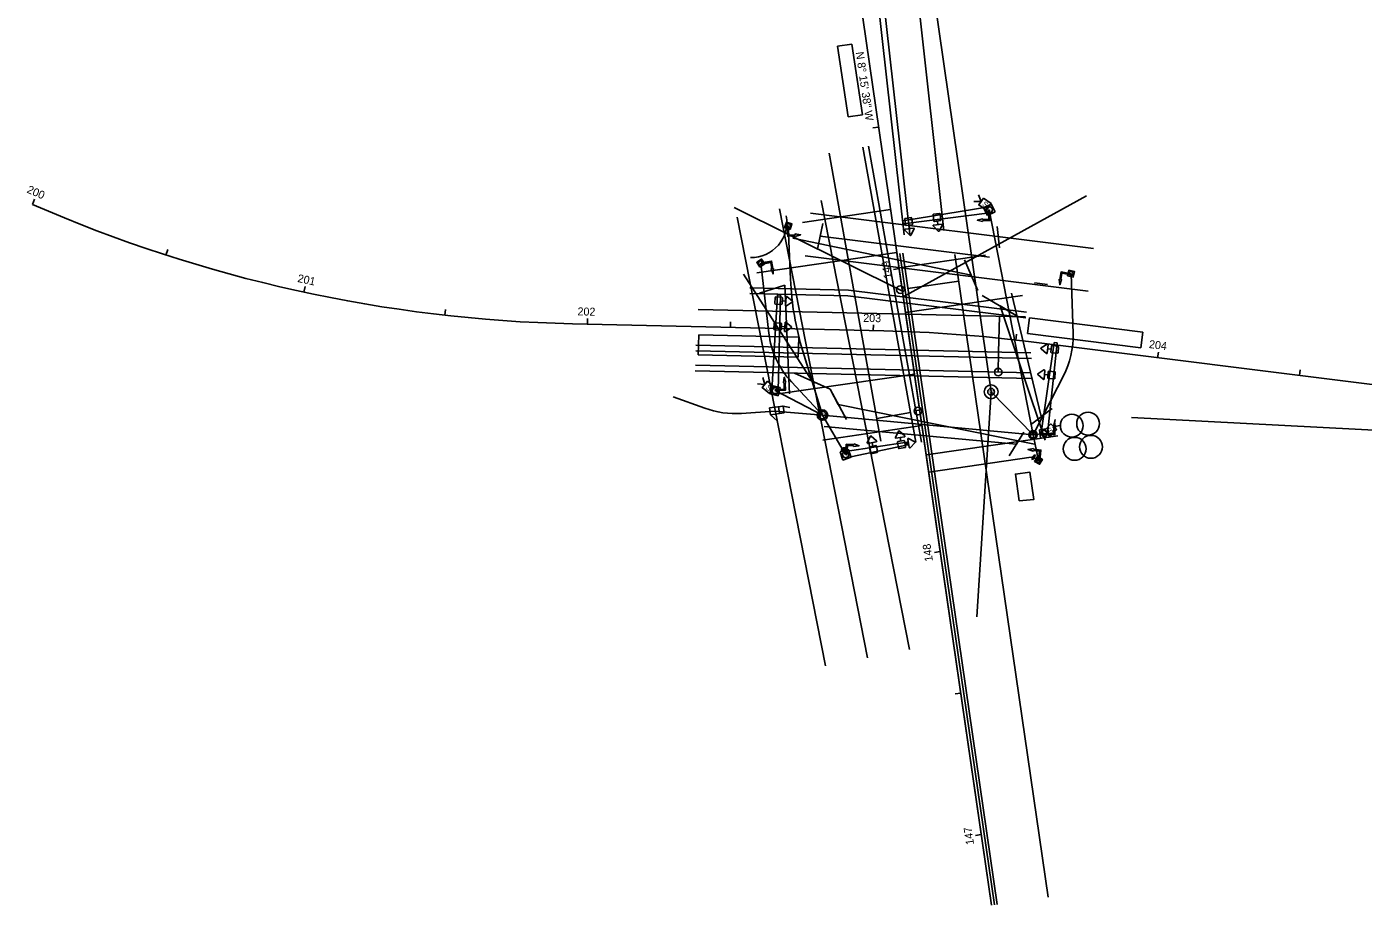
# Model space of a CAD drawing. Extents: x 1827063 to 1831280, y 711192 to 712800.
# Drawn here: x 1827845.4 to 1828313, y 711420.3 to 711727.6 of the extents above; entities that cross this region are included whole.
import ezdxf

# ---------------------------------------------------------------- set-up
doc = ezdxf.new("R2010")
doc.units = 0
for name, color, linetype in [('BR_P_Beam_Object', 7, 'Continuous'), ('BR_P_Gen_Joint_Filler', 7, 'Continuous'), ('Default', 7, 'Continuous'), ('DR_P_Storm_Sewer', 7, 'Continuous'), ('GE_P_CL_50', 7, 'Continuous'), ('PM_P_Crosswalk', 7, 'Continuous'), ('PV_P_Walk', 7, 'Continuous'), ('SC_Scratch6', 7, 'Continuous'), ('SG_P_Wiring', 7, 'Continuous'), ('SG_X_Controllers', 7, 'Continuous'), ('SG_X_Detection', 7, 'Continuous'), ('SG_X_Interconnect_Cable', 7, 'Continuous'), ('UT_P_Water', 7, 'Continuous'), ('UT_P_Water_Cells', 7, 'Continuous'), ('UT_P_Water_Text', 7, 'Continuous'), ('UT_X_Electric', 7, 'Continuous'), ('VG_X_Cells', 7, 'Continuous')]:
    doc.layers.add(name, color=color, linetype=linetype)

# ---------------------------------------------------------------- blocks, each defined once
blk = doc.blocks.new('SPOLE_1')
at = {"layer": 'Default'}
blk.add_circle((0, 0), 0.0138, dxfattribs=at)
blk = doc.blocks.new('Sighead')
at = {"layer": 'Default'}
for p, q in [((-0.03, 0.975), (-0.335, 0.569)), ((0.335, 0.569), (0.03, 0.975)), ((-0.305, 0.508), (0.305, 0.508)), ((-0.254, -0.216), (-0.254, 0.216)), ((-0.216, 0.254), (0.216, 0.254)), ((0, 0.508), (0, 0.254)), ((0.254, 0.216), (0.254, -0.216)), ((0.216, -0.254), (-0.216, -0.254))]:
    blk.add_line(p, q, dxfattribs=at)
for centre, start, end in [((0, 0.953), 36.8699, 143.1301), ((-0.305, 0.546), 143.1301, 270), ((-0.216, 0.216), 90, 180), ((0.216, 0.216), 0, 90), ((0.305, 0.546), 270, 36.8699), ((-0.216, -0.216), 180, 270), ((0.216, -0.216), 270, 0)]:
    blk.add_arc(centre, 0.0381, start, end, dxfattribs=at)
blk = doc.blocks.new('A$C70A22DE5')
at = {"layer": 'Default'}
for p, q in [((0, 0), (0.48, 0)), ((0.48, 0.24), (0.48, -0.24))]:
    blk.add_line(p, q, dxfattribs=at)
blk.add_arc((0.37, 0), 0.259, 294.3601, 65.6399, dxfattribs=at)

msp = doc.modelspace()

# ---------------------------------------------------------------- linework, layer by layer
at = {"layer": 'BR_P_Beam_Object'}
msp.add_line((1828154.76, 711660.82), (1828154.9, 711659.83), dxfattribs=at)
at = {"layer": 'BR_P_Gen_Joint_Filler'}
for centre in [(1828210.99, 711588.08), (1828216.7, 711588.78), (1828211.98, 711579.98), (1828217.69, 711580.68)]:
    msp.add_circle(centre, 4, dxfattribs=at)
at = {"layer": 'DR_P_Storm_Sewer'}
for p, q in [((1828182.93, 711420.35), (1828100.32, 711989.38)), ((1828143.42, 711692.49), (1828141.44, 711692.2)), ((1827847.36, 711665.45), (1827848.16, 711667.29)), ((1827894.09, 711647.74), (1827894.71, 711649.64)), ((1828150.6, 711643.01), (1828148.62, 711642.72)), ((1827942.36, 711634.78), (1827942.78, 711636.73)), ((1827991.69, 711626.7), (1827991.91, 711628.69)), ((1828036.34, 711623.69), (1828145.18, 711621.22)), ((1828041.57, 711623.57), (1828041.61, 711625.57)), ((1828091.56, 711622.44), (1828091.6, 711624.44)), ((1828141.54, 711621.31), (1828141.59, 711623.31)), ((1828191.41, 711618.03), (1828191.64, 711620.02)), ((1828195.88, 711617.49), (1828394.91, 711592.6)), ((1828241.03, 711611.84), (1828241.28, 711613.83)), ((1828290.64, 711605.64), (1828290.89, 711607.63)), ((1828157.79, 711593.53), (1828155.81, 711593.24)), ((1828164.97, 711544.05), (1828162.99, 711543.76)), ((1828172.15, 711494.57), (1828170.18, 711494.28)), ((1828179.34, 711445.09), (1828177.36, 711444.8))]:
    msp.add_line(p, q, dxfattribs=at)
for centre, start, end in [((1828047.65, 712123.23), 246.3698, 268.7041), ((1828133.88, 711121.68), 82.8726, 88.7041)]:
    msp.add_arc(centre, 499.67, start, end, dxfattribs=at)
at = {"layer": 'GE_P_CL_50'}
for p, q in [((1828123.3, 711666.79), (1828154.18, 711509.79)), ((1828093.97, 711661.02), (1828124.84, 711504.03)), ((1828093.97, 711661.02), (1828124.84, 711504.03)), ((1828108.68, 711663.91), (1828139.56, 711506.92)), ((1828108.68, 711663.91), (1828139.56, 711506.92)), ((1828108.68, 711663.91), (1828139.56, 711506.92)), ((1828108.68, 711663.91), (1828139.56, 711506.92))]:
    msp.add_line(p, q, dxfattribs=at)
at = {"layer": 'PM_P_Crosswalk'}
for p, q in [((1828132.68, 711633.51), (1828098.37, 711634.29)), ((1828132.83, 711635.51), (1828098.41, 711636.29)), ((1828132.68, 711633.51), (1828194.95, 711625.74)), ((1828132.83, 711635.51), (1828195.2, 711627.73))]:
    msp.add_line(p, q, dxfattribs=at)
at = {"layer": 'PV_P_Walk'}
for p, q in [((1828117.85, 711982.39), (1828154.28, 711655.03)), ((1828141.1, 711881.98), (1828166.21, 711656.36)), ((1828130.3, 711852.4), (1828152.3, 711654.81)), ((1828137.92, 711685.46), (1828156.42, 711582.33)), ((1828139.89, 711685.82), (1828158.46, 711582.28)), ((1828144.18, 711582.61), (1828126.11, 711683.35)), ((1828152.04, 711633.11), (1828216.18, 711668.44)), ((1828092.93, 711664.42), (1828151.76, 711635.08)), ((1828116.78, 711659.14), (1828147.61, 711663.62)), ((1828119.55, 711662.36), (1828218.55, 711650.02)), ((1828122.07, 711649.8), (1828123.93, 711658.79)), ((1828123.93, 711658.79), (1828123, 711654.3)), ((1828184.88, 711657.69), (1828185.71, 711650.32)), ((1828175.81, 711640.74), (1828113.44, 711653.69)), ((1828123, 711654.3), (1828182.19, 711646.95)), ((1828100.79, 711641.53), (1828149.79, 711648.64)), ((1828117.69, 711647.48), (1828216.7, 711635.13)), ((1828182.93, 711420.35), (1828149.82, 711648.42)), ((1828180.82, 711647.72), (1828150.56, 711643.33)), ((1828183.92, 711420.49), (1828150.86, 711648.23)), ((1828184.91, 711420.63), (1828151.85, 711648.38)), ((1828202.72, 711423.22), (1828170.09, 711647.96)), ((1828173.45, 711646.08), (1828178.16, 711635.4)), ((1828120.21, 711603.67), (1828096.19, 711641.04)), ((1828153.63, 711636.06), (1828171.45, 711638.65)), ((1828178.16, 711635.4), (1828175.81, 711640.74)), ((1828197.89, 711637.97), (1828202.47, 711637.4)), ((1828101.78, 711634.44), (1828110.6, 711637.17)), ((1828110.6, 711637.17), (1828112.19, 711599.25)), ((1828193.73, 711633.63), (1828152.83, 711627.69)), ((1828179.64, 711633.64), (1828192.17, 711626.25)), ((1828200.32, 711591.25), (1828189.91, 711634.44)), ((1828194.82, 711626.1), (1828080.28, 711628.69)), ((1828192.17, 711626.25), (1828185.9, 711629.95)), ((1828185.9, 711629.95), (1828201.62, 711583.06)), ((1828185.68, 711626.31), (1828185.4, 711613.8)), ((1828196.94, 711611.54), (1828079.44, 711614.19)), ((1828196.65, 711613.54), (1828079.48, 711616.19)), ((1828185.24, 711606.8), (1828185.4, 711613.8)), ((1828196.78, 711604.54), (1828079.28, 711607.2)), ((1828196.82, 711606.54), (1828079.32, 711609.2)), ((1828107.49, 711599.07), (1828155.96, 711606.11)), ((1828113.98, 711606.47), (1828126.43, 711600.87)), ((1828126.43, 711600.87), (1828120.21, 711603.67)), ((1828132.22, 711590.19), (1828126.43, 711600.87)), ((1828126.43, 711600.87), (1828129.32, 711595.53)), ((1828129.32, 711595.53), (1828198, 711581.61)), ((1828142.75, 711590.58), (1828154.56, 711592.7)), ((1828196.49, 711588.38), (1828204.14, 711594.11)), ((1828204.14, 711594.11), (1828200.32, 711591.25)), ((1828123.94, 711583.06), (1828158.58, 711588.09)), ((1828191.63, 711581.66), (1828124.35, 711587.74)), ((1828206.07, 711584.56), (1828160.06, 711577.88)), ((1828189.08, 711577.53), (1828194.18, 711585.79)), ((1828194.18, 711585.79), (1828191.63, 711581.66)), ((1828196.78, 711577.07), (1828160.93, 711571.86))]:
    msp.add_line(p, q, dxfattribs=at)
for centre in [(1828150.99, 711635.68), (1828185.24, 711606.8), (1828157.19, 711593.17)]:
    msp.add_circle(centre, 1.33, dxfattribs=at)
msp.add_arc((1828098.93, 711659.28), 12.39, 268.7041, 10.1696, dxfattribs=at)
at = {"layer": 'SC_Scratch6'}
for p, q in [((1828180.1, 711664.2), (1828182.77, 711665.56)), ((1828182.77, 711665.56), (1828184.14, 711662.89)), ((1828181.46, 711661.52), (1828180.1, 711664.2)), ((1828184.14, 711662.89), (1828181.46, 711661.52)), ((1828105.39, 711599.22), (1828106.07, 711602.15)), ((1828106.07, 711602.15), (1828108.99, 711601.47)), ((1828108.99, 711601.47), (1828108.31, 711598.54)), ((1828108.31, 711598.54), (1828105.39, 711599.22)), ((1828199.67, 711586.65), (1828202.64, 711587.08)), ((1828200.1, 711583.67), (1828199.67, 711586.65)), ((1828202.64, 711587.08), (1828203.07, 711584.11)), ((1828203.07, 711584.11), (1828200.1, 711583.67)), ((1828129.97, 711578.89), (1828132.81, 711579.85)), ((1828130.93, 711576.05), (1828129.97, 711578.89)), ((1828133.77, 711577.01), (1828130.93, 711576.05)), ((1828132.81, 711579.85), (1828133.77, 711577.01))]:
    msp.add_line(p, q, dxfattribs=at)
for points in [[(1828112.42, 711656.71), (1828110.53, 711657.36), (1828111.17, 711659.25), (1828113.07, 711658.61)], [(1828101.89, 711643.56), (1828100.79, 711645.23), (1828102.46, 711646.33), (1828103.56, 711644.66)], [(1828209.54, 711640.48), (1828209.96, 711642.44), (1828211.92, 711642.02), (1828211.49, 711640.06)], [(1828199.03, 711577.31), (1828200.74, 711576.27), (1828199.7, 711574.56), (1828197.99, 711575.6)]]:
    msp.add_lwpolyline(points, close=True, dxfattribs=at)
for centre in [(1828111.8, 711657.98), (1828102.17, 711644.94), (1828210.73, 711641.25), (1828199.37, 711575.94)]:
    msp.add_circle(centre, 0.727, dxfattribs=at)
for centre, start, end in [((1828182.12, 711663.54), 117.0406, 297.0406), ((1828182.12, 711663.54), 297.0406, 117.0406), ((1828107.19, 711600.35), 76.9134, 256.9134), ((1828107.19, 711600.35), 256.9134, 76.9134), ((1828201.37, 711585.38), 98.2605, 278.2605), ((1828201.37, 711585.38), 278.2605, 98.2605), ((1828131.87, 711577.95), 108.6322, 288.6322), ((1828131.87, 711577.95), 288.6322, 108.6322)]:
    msp.add_arc(centre, 1.09, start, end, dxfattribs=at)
at = {"layer": 'SG_P_Wiring'}
msp.add_line((1828197.45, 711584.9), (1828201.37, 711585.38), dxfattribs=at)
at = {"layer": 'SG_X_Controllers'}
for p, q in [((1828105.22, 711594.29), (1828110.01, 711594.95)), ((1828105.22, 711594.29), (1828105.55, 711591.9)), ((1828105.55, 711591.9), (1828110.34, 711592.56)), ((1828105.55, 711591.9), (1828107.9, 711589.77)), ((1828108.36, 711594.73), (1828108.68, 711592.33)), ((1828110.01, 711594.95), (1828110.34, 711592.56)), ((1828110.01, 711594.95), (1828112.37, 711594.44))]:
    msp.add_line(p, q, dxfattribs=at)
for centre in [(1828105.62, 711591.99), (1828109.94, 711594.86)]:
    msp.add_circle(centre, 0.0833, dxfattribs=at)
at = {"layer": 'SG_X_Detection'}
for p, q in [((1828129.05, 711720.79), (1828134, 711721.54)), ((1828132.79, 711696.07), (1828129.05, 711720.79)), ((1828134, 711721.54), (1828137.73, 711696.82)), ((1828137.73, 711696.82), (1828132.79, 711696.07)), ((1828176.7, 711666.48), (1828179.25, 711666.47)), ((1828178.31, 711668.83), (1828179.25, 711666.47)), ((1828195.47, 711620.31), (1828196.15, 711625.77)), ((1828196.15, 711625.77), (1828235.84, 711620.81)), ((1828080.33, 711612.79), (1828080.49, 711619.79)), ((1828080.49, 711619.79), (1828115.48, 711618.99)), ((1828115.48, 711618.99), (1828115.32, 711612)), ((1828235.16, 711615.35), (1828195.47, 711620.31)), ((1828235.84, 711620.81), (1828235.16, 711615.35)), ((1828115.32, 711612), (1828080.33, 711612.79)), ((1828102.88, 711604.96), (1828103.59, 711602.52)), ((1828101.06, 711602.76), (1828103.59, 711602.52)), ((1828205.15, 711590.21), (1828204.72, 711587.7)), ((1828207.2, 711588.24), (1828204.72, 711587.7))]:
    msp.add_line(p, q, dxfattribs=at)
for points in [[(1828180.05, 711667.64), (1828182.73, 711665.81), (1828181.13, 711663.46), (1828178.45, 711665.29)], [(1828104.5, 711603.61), (1828107.01, 711601.54), (1828105.19, 711599.35), (1828102.69, 711601.42)], [(1828205.75, 711586.72), (1828203.5, 711584.37), (1828201.44, 711586.34), (1828203.69, 711588.69)]]:
    msp.add_lwpolyline(points, close=True, dxfattribs=at)
at = {"layer": 'SG_X_Interconnect_Cable'}
for p, q in [((1828182.76, 711599.93), (1828149.39, 711832.03)), ((1828177.77, 711521.21), (1828182.76, 711599.93)), ((1828231.87, 711590.97), (1828404.99, 711581.92))]:
    msp.add_line(p, q, dxfattribs=at)
at = {"layer": 'UT_P_Water'}
for p, q in [((1828182.12, 711663.54), (1828197.45, 711584.9)), ((1828112.58, 711639.27), (1828111.8, 711657.98)), ((1828211.42, 711620.24), (1828210.73, 711641.25)), ((1828123.76, 711591.78), (1828116.9, 711614.14)), ((1828197.45, 711584.9), (1828208.08, 711605.46)), ((1828123.76, 711591.78), (1828107.19, 711600.35)), ((1828071.59, 711598.16), (1828082.56, 711594.23)), ((1828182.76, 711599.93), (1828197.45, 711584.9)), ((1828095.4, 711592.36), (1828107, 711593.2)), ((1828107, 711593.2), (1828123.76, 711591.78)), ((1828123.76, 711591.78), (1828131.87, 711577.95)), ((1828123.76, 711591.78), (1828197.45, 711584.9)), ((1828199.37, 711575.94), (1828197.45, 711584.9))]:
    msp.add_line(p, q, dxfattribs=at)
for points in [[(1828105.02, 711620.42), (1828102.17, 711644.94)], [(1828123.76, 711591.78), (1828112.9, 711603.39)]]:
    msp.add_lwpolyline(points, dxfattribs=at)
for centre, radius, start, end in [((1828212.5, 711643.48), 100, 182.4104, 197.0603), ((1828134.82, 711623.88), 30, 186.6123, 223.0804), ((1828181.44, 711619.25), 30, 332.641, 1.8972), ((1828093.21, 711622.28), 30, 249.2114, 274.1762)]:
    msp.add_arc(centre, radius, start, end, dxfattribs=at)
at = {"layer": 'UT_P_Water_Cells'}
for centre, radius in [((1828182.76, 711599.93), 2.42), ((1828182.76, 711599.93), 1.18), ((1828123.76, 711591.78), 1.83), ((1828123.76, 711591.78), 1.34), ((1828197.45, 711584.9), 1.46), ((1828197.45, 711584.9), 1.12), ((1828197.45, 711584.9), 1.12), ((1828197.45, 711584.9), 1.12), ((1828197.45, 711584.9), 1.12), ((1828197.45, 711584.9), 1.12)]:
    msp.add_circle(centre, radius, dxfattribs=at)
at = {"layer": 'UT_P_Water_Text'}
for p, q in [((1828151.86, 711659.66), (1828181.96, 711664.62)), ((1828182.27, 711662.46), (1828152.01, 711658.66)), ((1828152.01, 711658.66), (1828151.86, 711659.66)), ((1828106.1, 711600.39), (1828108.03, 711633.84)), ((1828108.03, 711633.84), (1828109.04, 711633.8)), ((1828109.04, 711633.8), (1828108.28, 711600.3)), ((1828200.28, 711585.51), (1828204.84, 711617.19)), ((1828205.84, 711617.07), (1828202.45, 711585.24)), ((1828204.84, 711617.19), (1828205.84, 711617.07)), ((1828131.68, 711579.02), (1828153.44, 711582.33)), ((1828153.61, 711581.33), (1828132.06, 711576.87)), ((1828153.44, 711582.33), (1828153.61, 711581.33))]:
    msp.add_line(p, q, dxfattribs=at)
for centre, start, end in [((1828182.12, 711663.54), 278.2767, 98.2767), ((1828107.19, 711600.35), 177.7307, 357.7307), ((1828201.37, 711585.38), 172.8889, 352.8889), ((1828131.87, 711577.95), 100.1859, 280.1859)]:
    msp.add_arc(centre, 1.09, start, end, dxfattribs=at)
at = {"layer": 'UT_X_Electric'}
msp.add_lwpolyline([(1828192.58, 711561.73), (1828197.77, 711562.29), (1828196.3, 711571.86), (1828191.26, 711571.15), (1828192.58, 711561.73)], dxfattribs=at)
at = {"layer": 'VG_X_Cells'}
for p, q in [((1828181.83, 711663.49), (1828182.23, 711663.51)), ((1828111.8, 711657.98), (1828111.4, 711657.96)), ((1828102.44, 711644.59), (1828102.37, 711644.99)), ((1828210.77, 711640.84), (1828210.83, 711641.23)), ((1828107.17, 711600.75), (1828107.19, 711600.35)), ((1828201.37, 711585.38), (1828201.35, 711584.98)), ((1828132.27, 711577.92), (1828131.87, 711577.95)), ((1828199.37, 711575.94), (1828199.76, 711575.89))]:
    msp.add_line(p, q, dxfattribs=at)
for points in [[(1828179.77, 711660.15), (1828181.98, 711660.24), (1828181.83, 711663.49)], [(1828182.23, 711663.51), (1828182.4, 711659.86), (1828179.79, 711659.75)], [(1828111.4, 711657.96), (1828111.62, 711654.31), (1828114.22, 711654.48)], [(1828114.2, 711654.87), (1828111.99, 711654.73), (1828111.8, 711657.98)], [(1828179.8, 711659.51), (1828177.89, 711659.91), (1828179.76, 711660.38), (1828179.77, 711660.15)], [(1828179.79, 711659.75), (1828179.8, 711659.51)], [(1828114.24, 711654.24), (1828116.09, 711654.84), (1828114.18, 711655.11), (1828114.2, 711654.87)], [(1828114.22, 711654.48), (1828114.24, 711654.24)], [(1828102.37, 711644.99), (1828105.97, 711645.61), (1828106.41, 711643.04)], [(1828106.02, 711642.97), (1828105.65, 711645.15), (1828102.44, 711644.59)], [(1828106.65, 711643.08), (1828106.49, 711641.14), (1828105.79, 711642.94), (1828106.02, 711642.97)], [(1828106.41, 711643.04), (1828106.65, 711643.08)], [(1828206.81, 711639.24), (1828206.58, 711639.27)], [(1828206.58, 711639.27), (1828206.76, 711637.33), (1828207.44, 711639.14), (1828207.21, 711639.18)], [(1828210.83, 711641.23), (1828207.22, 711641.82), (1828206.81, 711639.24)], [(1828207.21, 711639.18), (1828207.55, 711641.36), (1828210.77, 711640.84)], [(1828110.96, 711603.12), (1828110.39, 711604.98), (1828110.09, 711603.08), (1828110.33, 711603.09)], [(1828110.33, 711603.09), (1828110.42, 711600.88), (1828107.17, 711600.75)], [(1828107.19, 711600.35), (1828110.84, 711600.5), (1828110.73, 711603.11)], [(1828110.73, 711603.11), (1828110.96, 711603.12)], [(1828201.35, 711584.98), (1828205.01, 711584.85), (1828205.09, 711587.45)], [(1828204.69, 711587.47), (1828204.62, 711585.26), (1828201.37, 711585.38)], [(1828205.33, 711587.45), (1828204.91, 711589.35), (1828204.46, 711587.47), (1828204.69, 711587.47)], [(1828205.09, 711587.45), (1828205.33, 711587.45)], [(1828131.87, 711577.95), (1828132.09, 711581.6), (1828134.7, 711581.43)], [(1828134.71, 711581.67), (1828136.57, 711581.06), (1828134.65, 711580.8), (1828134.67, 711581.03)], [(1828134.7, 711581.43), (1828134.71, 711581.67)], [(1828134.67, 711581.03), (1828132.47, 711581.17), (1828132.27, 711577.92)], [(1828197.61, 711580.05), (1828195.68, 711579.77), (1828197.52, 711579.18), (1828197.54, 711579.41)], [(1828197.54, 711579.41), (1828199.74, 711579.17), (1828199.37, 711575.94)], [(1828197.58, 711579.81), (1828197.61, 711580.05)], [(1828199.76, 711575.89), (1828200.18, 711579.52), (1828197.58, 711579.81)]]:
    msp.add_lwpolyline(points, dxfattribs=at)

# ---------------------------------------------------------------- block references
at = {"layer": 'SC_Scratch6'}
for p, xscale, yscale, rotation in [((1828111.8, 711657.98), 52.49554118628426, 52.49554118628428, 161.16563581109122), ((1828102.17, 711644.94), 52.495541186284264, 52.49554118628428, 123.38965118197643), ((1828210.73, 711641.25), 52.49554118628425, 52.49554118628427, 77.81417194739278), ((1828199.37, 711575.94), 52.495541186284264, 52.49554118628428, -31.222800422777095)]:
    msp.add_blockref('SPOLE_1', p, dxfattribs=dict(at, xscale=xscale, yscale=yscale, rotation=rotation))
at = {"layer": 'SG_X_Detection'}
for p, xscale, yscale, rotation in [((1828131.87, 711577.95), 3.9417244, 3.941724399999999, 108.63804652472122), ((1828199.37, 711575.94), 3.9417244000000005, 3.9417243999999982, 148.77719958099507)]:
    msp.add_blockref('A$C70A22DE5', p, dxfattribs=dict(at, xscale=xscale, yscale=yscale, rotation=rotation))
at = {"layer": 'UT_P_Water'}
for p, xscale, yscale, rotation in [((1828153.92, 711659.45), 4.92125000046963, 4.92125000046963, -173.09870347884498), ((1828163.82, 711660.89), 4.921250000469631, 4.92125000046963, -173.09870347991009), ((1828108.45, 711631.78), 4.92125000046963, 4.92125000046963, -93.64624513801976), ((1828108.09, 711622.78), 4.921250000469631, 4.921250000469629, -93.64624514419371), ((1828205.04, 711614.72), 4.9212500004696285, 4.9212500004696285, 85.27969044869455), ((1828203.92, 711605.77), 4.921250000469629, 4.921250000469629, 86.42175382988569), ((1828151.4, 711581.45), 4.921250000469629, 4.921250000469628, 10.169643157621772), ((1828141.61, 711579.7), 4.921250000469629, 4.92125000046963, 11.001224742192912), ((1828151.4, 711581.45), 4.921250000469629, 4.9212500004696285, -79.83035684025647)]:
    msp.add_blockref('Sighead', p, dxfattribs=dict(at, xscale=xscale, yscale=yscale, rotation=rotation))

# ---------------------------------------------------------------- texts
at = {"layer": 'DR_P_Storm_Sewer'}
for s, rotation, p in [('N 8%%d 15\' 38" W', 278.2605, (1828135.38, 711718.66)), ('200', 336.3698, (1827845.22, 711669.67)), ('149', 98.2605, (1828148.06, 711639.67)), ('201', 347.8365, (1827939.95, 711638.37)), ('202', 358.7041, (1828038.05, 711626.65)), ('203', 358.7041, (1828138, 711624.39)), ('204', 352.8726, (1828237.86, 711615.26)), ('148', 98.2605, (1828162.42, 711540.75)), ('147', 98.2605, (1828176.8, 711441.67))]:
    msp.add_text(s, height=2.8, rotation=rotation, dxfattribs=at).set_placement(p)
at = {"layer": 'SG_X_Detection'}
for rotation, p in [(325.7069, (1828179.5, 711665.11)), (320.4315, (1828103.73, 711601.14)), (226.2299, (1828203.34, 711587.67))]:
    msp.add_text('S', height=1.95, rotation=rotation, dxfattribs=at).set_placement(p)
at = {"layer": 'UT_P_Water_Cells'}
for rotation, p in [(3.7551, (1828181.99, 711599.39)), (3.344, (1828122.99, 711591.25)), (356.5528, (1828196.62, 711584.47))]:
    msp.add_text('TR', height=0.962, rotation=rotation, dxfattribs=at).set_placement(p)

doc.saveas('drawing.dxf')
